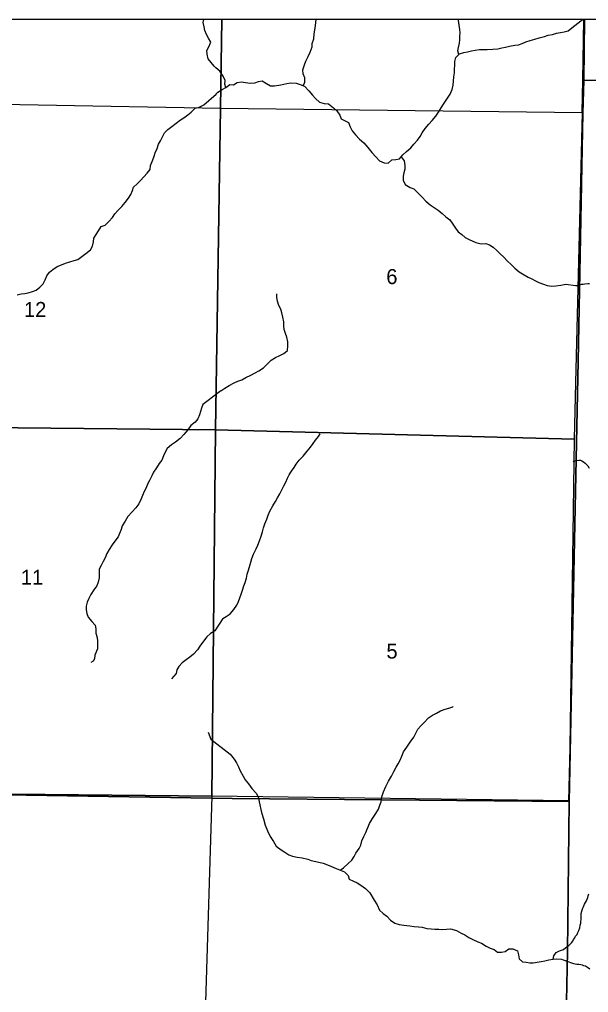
# Model space of a CAD drawing. Extents: x -10 to 158, y 8 to 33.
# Drawn here: x 39.989 to 41.577, y 19.238 to 21.955 of the extents above; entities that cross this region are included whole.
import ezdxf

# ---------------------------------------------------------------- set-up
doc = ezdxf.new("R2010")
doc.units = 0
for name, color, linetype in [('GM_X_Corporation', 7, 'Continuous'), ('GM_X_Minor_River', 7, 'Continuous'), ('GM_X_Section_Text', 7, 'Continuous')]:
    doc.layers.add(name, color=color, linetype=linetype)

msp = doc.modelspace()

# ---------------------------------------------------------------- linework, layer by layer
at = {"layer": 'GM_X_Corporation'}
for points in [[(41.5125, 19.0268), (41.5184, 19.3523), (41.5233, 19.7709), (41.5485, 21.0008), (41.5618, 21.6932), (41.564, 21.7852), (41.5663, 21.9552), (37.524, 21.9552), (37.524, 15.7497)], [(41.5125, 19.0268), (41.5184, 19.3523), (41.5233, 19.7709), (40.583, 19.7798), (39.4895, 19.7971), (38.0101, 19.8089), (37.524, 19.8122), (37.524, 15.7497)]]:
    msp.add_lwpolyline(points, dxfattribs=at)
for points in [[(41.5663, 21.9552), (37.524, 21.9552), (37.524, 19.8122), (38.0101, 19.8089), (39.4895, 19.7971), (40.583, 19.7798), (41.5233, 19.7709), (41.5485, 21.0008), (41.5618, 21.6932), (41.564, 21.7852)], [(40.5542, 21.9552), (39.5371, 21.9552), (39.5314, 21.7263), (40.5502, 21.7073)], [(41.564, 21.9552), (40.5542, 21.9552), (40.5502, 21.7073), (41.56, 21.6956), (41.5618, 21.7855)], [(41.4462, 15.1552), (44.324, 15.1552), (44.324, 21.9552), (41.5663, 21.9552), (41.564, 21.7852), (41.5618, 21.6932), (41.5485, 21.0008), (41.5233, 19.7709), (41.5184, 19.3523), (41.5125, 19.0268), (41.5025, 18.3092), (41.4916, 17.5539), (41.4842, 16.8508), (41.4581, 15.8355), (41.458, 15.832), (41.4573, 15.7877), (41.4556, 15.685), (41.4591, 15.5415), (41.4568, 15.5324), (41.4547, 15.4323)], [(44.324, 21.73), (44.324, 21.9552), (41.5663, 21.9552), (41.564, 21.7852), (42.3578, 21.7721), (42.4015, 21.7711)], [(44.324, 15.79), (44.324, 21.73), (42.4015, 21.7711), (42.3578, 21.7721), (41.564, 21.7852), (41.5618, 21.6932), (41.5485, 21.0008), (41.5233, 19.7709), (41.5184, 19.3523), (41.5125, 19.0268), (41.5025, 18.3092), (41.4916, 17.5539), (41.4842, 16.8508), (41.4581, 15.8355), (41.4922, 15.8348), (41.6019, 15.8337), (41.9512, 15.8301), (42.0434, 15.8291), (43.9186, 15.7973)], [(39.5314, 21.7263), (40.5502, 21.7073), (40.536, 20.8091), (39.5248, 20.8197)], [(40.5502, 21.7073), (41.56, 21.6956), (41.5411, 20.9404), (41.5375, 20.7831), (40.536, 20.8091)], [(40.536, 20.8091), (40.5256, 19.7858), (39.5015, 19.7966), (39.5248, 20.8197)], [(41.5375, 20.7831), (41.5249, 19.9223), (41.5214, 19.7729), (40.5256, 19.7858), (40.536, 20.8091)], [(40.5256, 19.7858), (40.494, 18.7574), (39.4803, 18.7786), (39.5015, 19.7966)]]:
    msp.add_lwpolyline(points, close=True, dxfattribs=at)
at = {"layer": 'GM_X_Minor_River'}
msp.add_line((41.5582, 21.9528), (41.5628, 21.9552), dxfattribs=at)
for points in [[(40.5323, 21.825), (40.5156, 21.8455), (40.5132, 21.858), (40.5115, 21.8682), (40.5171, 21.8785), (40.5226, 21.8922), (40.5164, 21.9031), (40.5113, 21.9133), (40.5066, 21.9242), (40.5042, 21.9347), (40.5021, 21.9465), (40.5034, 21.9552)], [(40.5343, 21.7425), (40.543, 21.7524), (40.5543, 21.7597), (40.5652, 21.7651), (40.5765, 21.7731), (40.5863, 21.7724), (40.5964, 21.7793), (40.6089, 21.7813), (40.6199, 21.7791), (40.6331, 21.7777), (40.6456, 21.7778), (40.6561, 21.7817), (40.6663, 21.7836), (40.6785, 21.7765), (40.6898, 21.7698), (40.7008, 21.7699), (40.7189, 21.7723), (40.7348, 21.7762), (40.7453, 21.7786), (40.7612, 21.7772), (40.7726, 21.7738), (40.7843, 21.7686), (40.7969, 21.7558), (40.8068, 21.7438), (40.8152, 21.734), (40.8262, 21.7239), (40.8398, 21.7209), (40.8519, 21.7199), (40.8652, 21.7086), (40.8751, 21.7004), (40.8835, 21.688), (40.887, 21.6778), (40.898, 21.6718), (40.9074, 21.6673), (40.9117, 21.6556), (40.9171, 21.6443), (40.9273, 21.633), (40.9376, 21.6213), (40.9502, 21.6104), (40.9612, 21.5976), (40.9723, 21.5837), (40.9833, 21.5713), (40.9936, 21.5608), (41.0065, 21.5548), (41.0178, 21.5534), (41.0287, 21.5629), (41.0393, 21.5645), (41.0495, 21.5657), (41.0592, 21.5768), (41.0694, 21.5863), (41.081, 21.5967), (41.0896, 21.6066), (41.0997, 21.618), (41.1069, 21.6287), (41.1128, 21.6382), (41.1214, 21.6508), (41.1312, 21.663), (41.1413, 21.6733), (41.1514, 21.6847), (41.1608, 21.6988), (41.1664, 21.7087), (41.1724, 21.7189), (41.1814, 21.7327), (41.1907, 21.7464), (41.197, 21.76), (41.1992, 21.7718), (41.2013, 21.7949), (41.2028, 21.8059), (41.2031, 21.8165), (41.2038, 21.8275), (41.2045, 21.8381), (41.207, 21.8488), (41.2175, 21.8591), (41.2296, 21.8626), (41.2398, 21.8649), (41.2511, 21.8677), (41.2613, 21.8693), (41.2734, 21.8709), (41.2832, 21.8709), (41.2942, 21.8714), (41.3104, 21.8719), (41.3244, 21.8735), (41.3349, 21.8759), (41.3455, 21.8779), (41.3568, 21.8806), (41.3712, 21.883), (41.3818, 21.8842), (41.3923, 21.8881), (41.4025, 21.8923), (41.4145, 21.8966), (41.4277, 21.9005), (41.4394, 21.9036), (41.4545, 21.9075), (41.4647, 21.911), (41.4768, 21.9133), (41.4881, 21.9168), (41.499, 21.9188), (41.5096, 21.9208), (41.5202, 21.9235), (41.5307, 21.9319), (41.5558, 21.9513)], [(40.7812, 21.77), (40.7858, 21.7804), (40.7853, 21.7921), (40.7811, 21.8035), (40.7799, 21.8148), (40.7843, 21.8281), (40.788, 21.8387), (40.7944, 21.8513), (40.8007, 21.8635), (40.8063, 21.8783), (40.8062, 21.8877), (40.8103, 21.9014), (40.8117, 21.9151), (40.8142, 21.931), (40.8164, 21.9465), (40.8172, 21.9552)], [(41.2154, 21.857), (41.2129, 21.8674), (41.2148, 21.8772), (41.2173, 21.8886), (41.218, 21.8985), (41.2183, 21.9083), (41.219, 21.9178), (41.2182, 21.9276), (41.2166, 21.9394), (41.2146, 21.9519), (41.214, 21.9552)], [(41.5558, 21.9513), (41.5582, 21.9528)], [(40.5652, 21.7651), (40.5621, 21.7749), (40.5632, 21.7851), (40.5574, 21.7972), (40.5479, 21.8104), (40.5368, 21.8201), (40.5323, 21.825)], [(39.9826, 21.1859), (39.994, 21.1887), (40.0038, 21.19), (40.0136, 21.192), (40.0253, 21.1952), (40.0359, 21.1996), (40.0457, 21.2073), (40.055, 21.2169), (40.0609, 21.2284), (40.0657, 21.2394), (40.0728, 21.2494), (40.0825, 21.2571), (40.0946, 21.2649), (40.1066, 21.2703), (40.1175, 21.2743), (40.1296, 21.2779), (40.1417, 21.2819), (40.1519, 21.2847), (40.1737, 21.3017), (40.1876, 21.3121), (40.1931, 21.3217), (40.1956, 21.3346), (40.1966, 21.3444), (40.2033, 21.3548), (40.2092, 21.3647), (40.2174, 21.3766), (40.228, 21.3805), (40.2381, 21.3913), (40.2485, 21.4017), (40.2548, 21.412), (40.2634, 21.422), (40.2743, 21.4327), (40.2844, 21.4439), (40.2937, 21.4558), (40.2996, 21.4668), (40.3044, 21.4771), (40.3073, 21.4867), (40.317, 21.4966), (40.3268, 21.5059), (40.3361, 21.5159), (40.3455, 21.5259), (40.354, 21.5362), (40.355, 21.5472), (40.3609, 21.5636), (40.3649, 21.5731), (40.3674, 21.583), (40.373, 21.5948), (40.377, 21.6067), (40.3825, 21.6162), (40.3881, 21.6273), (40.394, 21.6387), (40.403, 21.6483), (40.4146, 21.6565), (40.4262, 21.6657), (40.4382, 21.675), (40.448, 21.6808), (40.4585, 21.689), (40.4683, 21.6967), (40.4795, 21.7071), (40.4905, 21.7107), (40.5033, 21.7169), (40.5383, 21.747), (40.5373, 21.7462)], [(40.5373, 21.7462), (40.543, 21.7524)], [(41.0545, 21.5714), (41.0627, 21.5602), (41.0643, 21.5473), (41.0648, 21.5367), (41.0618, 21.5272), (41.0596, 21.5173), (41.0601, 21.5064), (41.0658, 21.4939), (41.0799, 21.4857), (41.0897, 21.482), (41.1004, 21.4714), (41.1125, 21.459), (41.1236, 21.4481), (41.1357, 21.4376), (41.146, 21.4297), (41.1577, 21.4223), (41.1684, 21.4129), (41.179, 21.4042), (41.19, 21.3956), (41.1988, 21.3836), (41.2057, 21.3719), (41.2137, 21.3621), (41.2236, 21.3542), (41.2331, 21.3463), (41.2437, 21.3411), (41.263, 21.3325), (41.2774, 21.3285), (41.2906, 21.3297), (41.3012, 21.326), (41.3115, 21.3197), (41.3214, 21.3099), (41.3309, 21.3005), (41.3404, 21.2919), (41.351, 21.2802), (41.3613, 21.2712), (41.3716, 21.2603), (41.3841, 21.2505), (41.3974, 21.2423), (41.4092, 21.2356), (41.4186, 21.2311), (41.4289, 21.2251), (41.4384, 21.2203), (41.4512, 21.2158), (41.4622, 21.2121), (41.4751, 21.2103), (41.486, 21.2112), (41.5, 21.2132), (41.514, 21.2155), (41.5413, 21.2119), (41.5458, 21.2124)], [(41.5458, 21.2124), (41.5577, 21.2161), (41.5619, 21.2161), (41.5668, 21.2165), (41.5751, 21.2174), (41.5796, 21.2178)], [(40.551, 20.9185), (40.5625, 20.9257), (40.5745, 20.9326), (40.5884, 20.9403), (40.5982, 20.9449), (40.6092, 20.9488), (40.6208, 20.9553), (40.6348, 20.9615), (40.6468, 20.968), (40.6566, 20.9742), (40.6698, 20.9826), (40.6796, 20.9914), (40.6912, 21.0036), (40.7032, 21.0109), (40.7153, 21.0163), (40.727, 21.0224), (40.7371, 21.0305), (40.7382, 21.0441), (40.7381, 21.0551), (40.7354, 21.0676), (40.7315, 21.0778), (40.728, 21.0895), (40.7272, 21.0993), (40.7264, 21.111), (40.7236, 21.1239), (40.7217, 21.1356), (40.7186, 21.1458), (40.7128, 21.1568), (40.7094, 21.1681), (40.7074, 21.1787), (40.7077, 21.1882), (40.7073, 21.1889)], [(40.551, 20.9185), (40.5115, 20.8883), (40.501, 20.8802), (40.4969, 20.8699), (40.4911, 20.8508), (40.4867, 20.8402), (40.4789, 20.8306), (40.4676, 20.8209), (40.4591, 20.8091), (40.4475, 20.796), (40.4374, 20.7849), (40.4247, 20.7748), (40.4134, 20.7671), (40.4014, 20.7567), (40.3955, 20.7464), (40.3914, 20.7365), (40.3867, 20.7243), (40.3792, 20.7147), (40.3714, 20.7028), (40.3632, 20.6906), (40.358, 20.6803), (40.3521, 20.6681), (40.3466, 20.6577), (40.3422, 20.6474), (40.3374, 20.6372), (40.3326, 20.6261), (40.3289, 20.6166), (40.3223, 20.6021), (40.3141, 20.591), (40.3033, 20.5802), (40.2917, 20.5675), (40.2835, 20.5541), (40.2757, 20.5411), (40.2728, 20.5312), (40.2684, 20.5198), (40.264, 20.5099), (40.2547, 20.498), (40.2472, 20.4881), (40.2391, 20.4754), (40.2328, 20.4636), (40.2284, 20.4518), (40.2221, 20.4411), (40.2169, 20.43), (40.2117, 20.4197), (40.2111, 20.408), (40.2113, 20.3959), (40.2084, 20.3841), (40.2044, 20.3738), (40.1962, 20.3619), (40.188, 20.3493), (40.1821, 20.3382), (40.1781, 20.3279), (40.1748, 20.3165), (40.1749, 20.3063), (40.1766, 20.2961), (40.1805, 20.2859), (40.1909, 20.2743), (40.2005, 20.2639), (40.2018, 20.2533), (40.2019, 20.2412), (40.2059, 20.2295), (40.2068, 20.2193), (40.2069, 20.2072), (40.2063, 20.1977), (40.199, 20.1798), (40.1987, 20.1695), (40.1942, 20.1632), (40.1878, 20.1595)], [(40.5562, 20.2818), (40.5663, 20.288), (40.5769, 20.2956), (40.5874, 20.3074), (40.5956, 20.3196), (40.6001, 20.3295), (40.6038, 20.3401), (40.6079, 20.35), (40.6119, 20.3618), (40.6149, 20.3732), (40.6186, 20.3827), (40.6227, 20.3952), (40.6249, 20.4058), (40.6286, 20.4168), (40.6345, 20.4396), (40.6374, 20.4499), (40.6426, 20.462), (40.6493, 20.4765), (40.6542, 20.4871), (40.659, 20.4993), (40.6638, 20.5122), (40.6672, 20.5247), (40.6705, 20.5353), (40.6742, 20.5463), (40.679, 20.5592), (40.6831, 20.571), (40.6876, 20.5824), (40.6962, 20.5965), (40.7033, 20.609), (40.7092, 20.6189), (40.7152, 20.6307), (40.7208, 20.6414), (40.7264, 20.6528), (40.732, 20.6627), (40.7372, 20.6737), (40.7417, 20.6839), (40.7484, 20.6935), (40.7552, 20.7037), (40.7615, 20.7136), (40.7694, 20.7247), (40.781, 20.7358), (40.7919, 20.7495), (40.8009, 20.7605), (40.8091, 20.7708), (40.8151, 20.7803), (40.8234, 20.7902), (40.8282, 20.7975)], [(41.534, 20.7198), (41.5381, 20.7223), (41.5418, 20.7239), (41.5505, 20.7247), (41.5547, 20.7244), (41.5585, 20.7229), (41.5634, 20.7199), (41.5676, 20.7162), (41.5749, 20.7083), (41.5787, 20.7023)], [(40.5562, 20.2818), (40.5343, 20.2481), (40.5219, 20.2407), (40.5121, 20.2307), (40.5024, 20.2189), (40.4924, 20.2054), (40.4861, 20.1948), (40.4749, 20.1828), (40.4643, 20.1747), (40.4542, 20.1666), (40.4426, 20.1581), (40.434, 20.1485), (40.4284, 20.139), (40.4259, 20.1291), (40.4136, 20.1133)], [(40.884, 19.5794), (40.8937, 19.586), (40.9065, 19.5979), (40.917, 19.6074), (40.923, 19.6177), (40.9282, 19.6272), (40.9368, 19.6401), (40.9417, 19.6496), (40.945, 19.661), (40.9502, 19.6736), (40.9554, 19.685), (40.9658, 19.7093), (40.9744, 19.7234), (40.9838, 19.7375), (40.9909, 19.7496), (40.995, 19.761), (40.9987, 19.7705), (41.0005, 19.7842), (41.0053, 19.7982), (41.0116, 19.8127), (41.0191, 19.8282), (41.0269, 19.8419), (41.034, 19.8549), (41.04, 19.8667), (41.0463, 19.8765), (41.0516, 19.8864), (41.0564, 19.8975), (41.0612, 19.9096), (41.0702, 19.9233), (41.0796, 19.937), (41.0897, 19.9504), (41.0957, 19.9618), (41.1009, 19.9728), (41.1091, 19.9823), (41.1185, 19.9919), (41.1305, 20.0052), (41.1414, 20.0121), (41.1527, 20.0179), (41.164, 20.0244), (41.1768, 20.0287), (41.1878, 20.0314), (41.1987, 20.0356), (41.1998, 20.0375)], [(40.5158, 19.9649), (40.5234, 19.945), (40.5768, 19.9036), (40.5886, 19.8897), (40.5951, 19.8795), (40.6001, 19.8678), (40.6051, 19.8565), (40.6131, 19.8422), (40.6192, 19.832), (40.628, 19.8203), (40.6379, 19.8079), (40.6493, 19.794), (40.6558, 19.7827), (40.6582, 19.7702), (40.6648, 19.7407), (40.6702, 19.7226), (40.6749, 19.7052), (40.6814, 19.6889), (40.6887, 19.6735), (40.6979, 19.6591), (40.7051, 19.6467), (40.7192, 19.6366), (40.7298, 19.6295), (40.7404, 19.622), (40.7514, 19.6183), (40.7643, 19.6157), (40.7779, 19.6139), (40.7934, 19.6099), (40.8029, 19.6062), (40.8158, 19.6032), (40.8362, 19.5992), (40.8491, 19.5944), (40.8601, 19.5896), (40.8733, 19.5836), (40.8961, 19.5747), (40.906, 19.5645), (40.9094, 19.554), (40.9212, 19.5487), (40.9318, 19.5439), (40.9413, 19.5379), (40.9546, 19.5278), (40.9671, 19.5162), (40.9793, 19.4958), (40.9874, 19.4822), (40.9943, 19.4679), (41.0038, 19.4585), (41.0144, 19.451), (41.0247, 19.4401), (41.0365, 19.4318), (41.0486, 19.4278), (41.0614, 19.426), (41.0788, 19.4235), (41.0902, 19.4224), (41.1023, 19.421), (41.1129, 19.4203), (41.1261, 19.4162), (41.1378, 19.4152), (41.148, 19.4145), (41.1598, 19.415), (41.1707, 19.4139), (41.1809, 19.4148), (41.1923, 19.4156), (41.2085, 19.4108), (41.2214, 19.4037), (41.232, 19.3989), (41.243, 19.3914), (41.254, 19.3858), (41.2684, 19.3795), (41.2783, 19.3757), (41.2912, 19.3671), (41.303, 19.3619), (41.3136, 19.3575), (41.3231, 19.35), (41.3344, 19.35), (41.3442, 19.352), (41.3544, 19.3597), (41.3661, 19.3597), (41.3786, 19.3542), (41.3821, 19.3432), (41.3833, 19.3319), (41.3931, 19.3236), (41.4034, 19.3222), (41.4132, 19.3207), (41.423, 19.3208), (41.4449, 19.324), (41.4555, 19.3263), (41.4668, 19.3287), (41.4785, 19.3307), (41.4891, 19.3315), (41.502, 19.3308), (41.5066, 19.3292)], [(41.5073, 19.358), (41.518, 19.3666), (41.5221, 19.3693), (41.53, 19.3766), (41.5333, 19.3811), (41.5355, 19.3857), (41.5389, 19.3903), (41.5411, 19.3948), (41.5452, 19.4002), (41.5474, 19.4055), (41.55, 19.4112), (41.5526, 19.4188), (41.5544, 19.4257), (41.5555, 19.4313), (41.5558, 19.4363), (41.5565, 19.442), (41.5565, 19.4457), (41.5568, 19.4495), (41.5568, 19.4545), (41.5571, 19.4586), (41.5586, 19.4647), (41.5608, 19.4712), (41.5619, 19.475), (41.5641, 19.4795), (41.5659, 19.4845), (41.5685, 19.4894), (41.5715, 19.494), (41.5752, 19.5035), (41.5759, 19.5077), (41.5777, 19.5134)], [(41.4785, 19.3307), (41.4805, 19.3398), (41.4871, 19.3493), (41.4963, 19.3544), (41.5073, 19.358)], [(41.5066, 19.3292), (41.5199, 19.3242), (41.5298, 19.3205), (41.5358, 19.3187), (41.5404, 19.318), (41.5449, 19.3169), (41.5506, 19.3165), (41.5555, 19.3158), (41.5597, 19.3147), (41.5635, 19.3136), (41.5688, 19.3118), (41.5745, 19.3084), (41.581, 19.304)]]:
    msp.add_lwpolyline(points, dxfattribs=at)

# ---------------------------------------------------------------- texts
at = {"layer": 'GM_X_Section_Text'}
for s, height, p in [('6', 0.0419, (41.0128, 21.2161)), ('12', 0.04186, (40.0015, 21.1243)), ('11', 0.04186, (39.9928, 20.3765)), ('5', 0.0419, (41.0132, 20.1703))]:
    msp.add_text(s, height=height, rotation=0, dxfattribs=at).set_placement(p)

doc.saveas('drawing.dxf')
